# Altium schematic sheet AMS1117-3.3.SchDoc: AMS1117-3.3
size 296 x 210 mm; Revision: 1.0; DocumentSize: A4
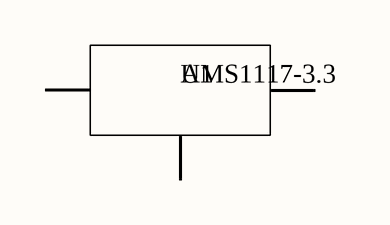
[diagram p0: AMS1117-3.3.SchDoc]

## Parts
U1  value AMS1117-3.3

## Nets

Not connected (* = marked no-connect by the designer): U1 1(GND) 2(VOUT) 3(VIN)

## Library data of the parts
U1 = AMS1117-3.3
